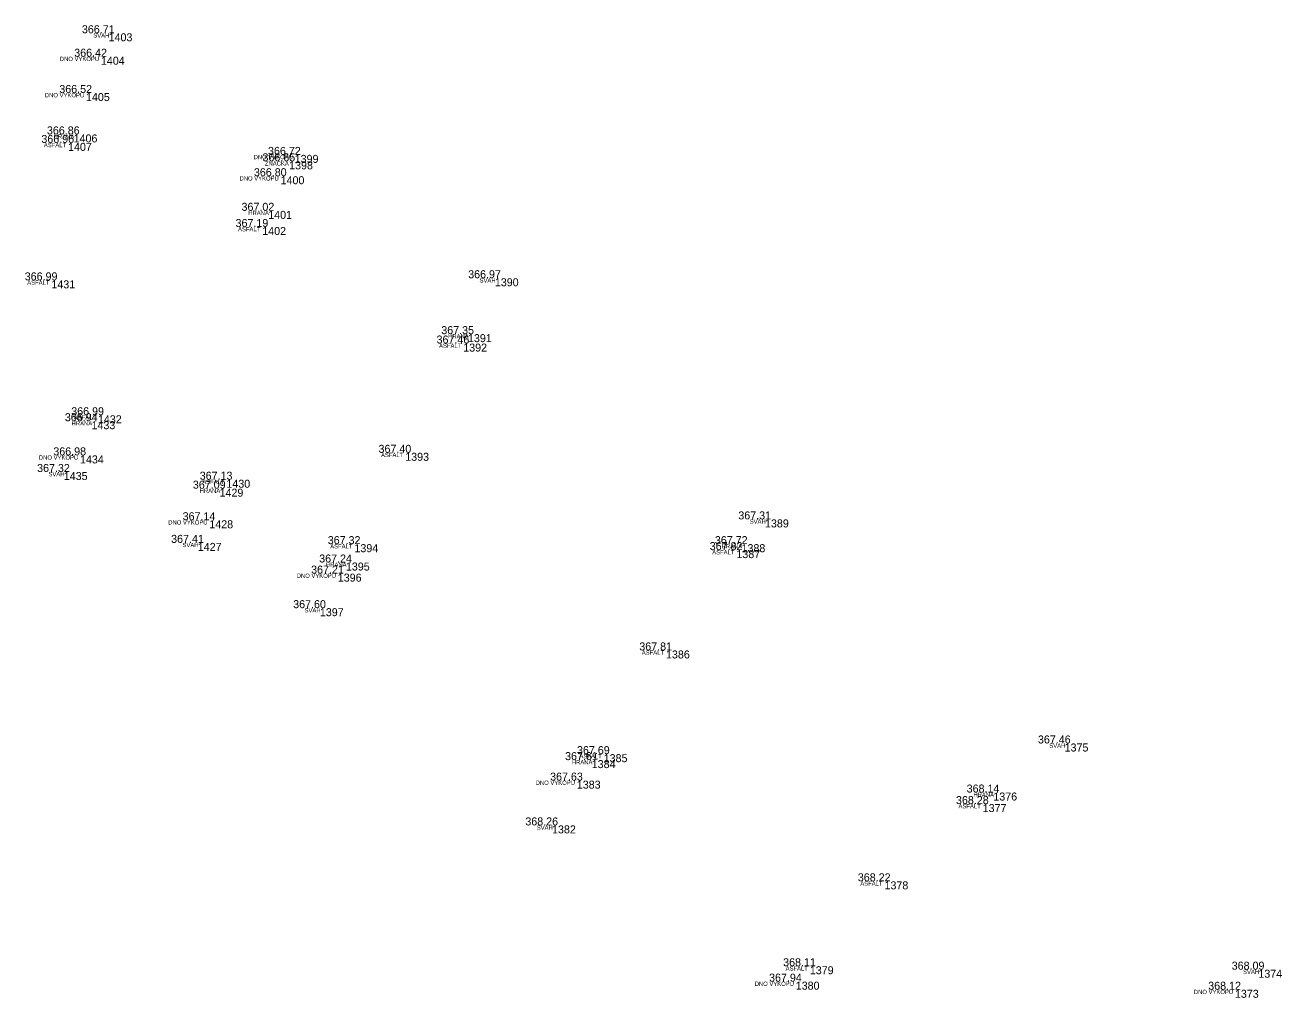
# Model space of a CAD drawing. Extents: x -597865 to -597551, y -1151663 to -1149883.
# Drawn here: x -597649.41 to -597619.96, y -1150439.73 to -1150416.94 of the extents above; entities that cross this region are included whole.
import ezdxf

# ---------------------------------------------------------------- set-up
doc = ezdxf.new("R2010")
doc.units = 0
for name, color, linetype in [('Vrstva 11', 7, 'Continuous'), ('Vrstva 12', 7, 'Continuous'), ('Vrstva 13', 7, 'Continuous'), ('Vrstva 14', 7, 'Continuous')]:
    doc.layers.add(name, color=color, linetype=linetype)

msp = doc.modelspace()

# ---------------------------------------------------------------- linework, layer by layer
at = {"layer": 'Vrstva 11'}
for p, q in [((-597647.45, -1150417.13), (-597647.45, -1150417.13)), ((-597647.63, -1150417.68), (-597647.63, -1150417.68)), ((-597647.98, -1150418.53), (-597647.98, -1150418.53)), ((-597648.4, -1150419.7), (-597648.4, -1150419.7)), ((-597648.27, -1150419.5), (-597648.27, -1150419.5)), ((-597643.09, -1150419.98), (-597643.09, -1150419.98)), ((-597643.22, -1150420.13), (-597643.22, -1150420.13)), ((-597643.42, -1150420.48), (-597643.42, -1150420.48)), ((-597643.71, -1150421.29), (-597643.71, -1150421.29)), ((-597643.85, -1150421.67), (-597643.85, -1150421.67)), ((-597648.79, -1150422.92), (-597648.79, -1150422.92)), ((-597638.4, -1150422.87), (-597638.4, -1150422.87)), ((-597639.14, -1150424.4), (-597639.14, -1150424.4)), ((-597639.03, -1150424.18), (-597639.03, -1150424.18)), ((-597647.85, -1150426.22), (-597647.85, -1150426.22)), ((-597647.7, -1150426.08), (-597647.7, -1150426.08)), ((-597648.12, -1150427.02), (-597648.12, -1150427.02)), ((-597640.5, -1150426.96), (-597640.5, -1150426.96)), ((-597648.5, -1150427.41), (-597648.5, -1150427.41)), ((-597644.69, -1150427.59), (-597644.69, -1150427.59)), ((-597644.85, -1150427.8), (-597644.85, -1150427.8)), ((-597645.09, -1150428.54), (-597645.09, -1150428.54)), ((-597632.07, -1150428.52), (-597632.07, -1150428.52)), ((-597645.36, -1150429.07), (-597645.36, -1150429.07)), ((-597641.69, -1150429.1), (-597641.69, -1150429.1)), ((-597632.62, -1150429.1), (-597632.62, -1150429.1)), ((-597632.74, -1150429.24), (-597632.74, -1150429.24)), ((-597641.89, -1150429.53), (-597641.89, -1150429.53)), ((-597642.08, -1150429.79), (-597642.08, -1150429.79)), ((-597642.5, -1150430.6), (-597642.5, -1150430.6)), ((-597634.39, -1150431.59), (-597634.39, -1150431.59)), ((-597625.05, -1150433.77), (-597625.05, -1150433.77)), ((-597636.13, -1150434.16), (-597636.13, -1150434.16)), ((-597635.85, -1150434.02), (-597635.85, -1150434.02)), ((-597636.48, -1150434.64), (-597636.48, -1150434.64)), ((-597626.72, -1150434.92), (-597626.72, -1150434.92)), ((-597626.97, -1150435.19), (-597626.97, -1150435.19)), ((-597637.06, -1150435.69), (-597637.06, -1150435.69)), ((-597629.27, -1150437), (-597629.27, -1150437)), ((-597631.02, -1150438.99), (-597631.02, -1150438.99)), ((-597620.51, -1150439.07), (-597620.51, -1150439.07)), ((-597631.35, -1150439.35), (-597631.35, -1150439.35)), ((-597621.06, -1150439.54), (-597621.06, -1150439.54))]:
    msp.add_line(p, q, dxfattribs=at)

# ---------------------------------------------------------------- texts
at = {"layer": 'Vrstva 12'}
for s, p in [('366.71 ', (-597648.075, -1150417.13)), ('366.42 ', (-597648.255, -1150417.68)), ('366.52 ', (-597648.605, -1150418.53)), ('366.86 ', (-597648.895, -1150419.5)), ('366.96 ', (-597649.025, -1150419.7)), ('366.65 ', (-597643.845, -1150420.13)), ('366.72 ', (-597643.715, -1150419.98)), ('366.80 ', (-597644.045, -1150420.48)), ('367.02 ', (-597644.335, -1150421.29)), ('367.19 ', (-597644.475, -1150421.67)), ('366.97 ', (-597639.025, -1150422.87)), ('366.99 ', (-597649.415, -1150422.92)), ('367.35 ', (-597639.655, -1150424.18)), ('367.46 ', (-597639.765, -1150424.4)), ('366.99 ', (-597648.325, -1150426.08)), ('366.94 ', (-597648.475, -1150426.22)), ('367.40 ', (-597641.125, -1150426.96)), ('366.98 ', (-597648.745, -1150427.02)), ('367.32 ', (-597649.125, -1150427.41)), ('367.13 ', (-597645.315, -1150427.59)), ('367.09 ', (-597645.475, -1150427.8)), ('367.14 ', (-597645.715, -1150428.54)), ('367.31 ', (-597632.695, -1150428.52)), ('367.41 ', (-597645.985, -1150429.07)), ('367.32 ', (-597642.315, -1150429.1)), ('367.82 ', (-597633.365, -1150429.24)), ('367.72 ', (-597633.245, -1150429.1)), ('367.24 ', (-597642.515, -1150429.53)), ('367.21 ', (-597642.705, -1150429.79)), ('367.60 ', (-597643.125, -1150430.6)), ('367.81 ', (-597635.015, -1150431.59)), ('367.46 ', (-597625.675, -1150433.77)), ('367.69 ', (-597636.475, -1150434.02)), ('367.61 ', (-597636.755, -1150434.16)), ('367.63 ', (-597637.105, -1150434.64)), ('368.14 ', (-597627.345, -1150434.92)), ('368.28 ', (-597627.595, -1150435.19)), ('368.26 ', (-597637.685, -1150435.69)), ('368.22 ', (-597629.895, -1150437)), ('368.11 ', (-597631.645, -1150438.99)), ('368.09 ', (-597621.135, -1150439.07)), ('367.94 ', (-597631.975, -1150439.35)), ('368.12 ', (-597621.685, -1150439.54))]:
    msp.add_text(s, height=0.1875, dxfattribs=at).set_placement(p)
at = {"layer": 'Vrstva 13'}
for s, p in [('1403', (-597647.45, -1150417.318)), ('1404', (-597647.63, -1150417.867)), ('1405', (-597647.98, -1150418.718)), ('1407', (-597648.4, -1150419.887)), ('1406', (-597648.27, -1150419.688)), ('1399', (-597643.09, -1150420.167)), ('1398', (-597643.22, -1150420.318)), ('1400', (-597643.42, -1150420.667)), ('1401', (-597643.71, -1150421.478)), ('1402', (-597643.85, -1150421.857)), ('1431', (-597648.79, -1150423.107)), ('1390', (-597638.4, -1150423.058)), ('1392', (-597639.14, -1150424.588)), ('1391', (-597639.03, -1150424.367)), ('1433', (-597647.85, -1150426.407)), ('1432', (-597647.7, -1150426.268)), ('1434', (-597648.12, -1150427.208)), ('1393', (-597640.5, -1150427.147)), ('1435', (-597648.5, -1150427.597)), ('1430', (-597644.69, -1150427.778)), ('1429', (-597644.85, -1150427.988)), ('1428', (-597645.09, -1150428.728)), ('1389', (-597632.07, -1150428.708)), ('1427', (-597645.36, -1150429.258)), ('1394', (-597641.69, -1150429.288)), ('1388', (-597632.62, -1150429.288)), ('1387', (-597632.74, -1150429.427)), ('1395', (-597641.89, -1150429.718)), ('1396', (-597642.08, -1150429.978)), ('1397', (-597642.5, -1150430.788)), ('1386', (-597634.39, -1150431.778)), ('1375', (-597625.05, -1150433.958)), ('1384', (-597636.13, -1150434.347)), ('1385', (-597635.85, -1150434.208)), ('1383', (-597636.48, -1150434.828)), ('1376', (-597626.72, -1150435.107)), ('1377', (-597626.97, -1150435.377)), ('1382', (-597637.06, -1150435.877)), ('1378', (-597629.27, -1150437.188)), ('1379', (-597631.02, -1150439.177)), ('1374', (-597620.51, -1150439.258)), ('1380', (-597631.35, -1150439.538)), ('1373', (-597621.06, -1150439.728))]:
    msp.add_text(s, height=0.1875, dxfattribs=at).set_placement(p)
at = {"layer": 'Vrstva 14'}
for s, p in [('SVAH', (-597647.808, -1150417.23)), ('DNO VYKOPU', (-597648.593, -1150417.78)), ('DNO VYKOPU', (-597648.943, -1150418.63)), ('ASFALT', (-597648.967, -1150419.8)), ('HRANA', (-597648.737, -1150419.6)), ('DNO VYKOPU', (-597644.052, -1150420.08)), ('ZNACKA', (-597643.787, -1150420.23)), ('DNO VYKOPU', (-597644.383, -1150420.58)), ('HRANA', (-597644.177, -1150421.39)), ('ASFALT', (-597644.417, -1150421.77)), ('ASFALT', (-597649.357, -1150423.02)), ('SVAH', (-597638.758, -1150422.97)), ('ASFALT', (-597639.707, -1150424.5)), ('HRANA', (-597639.497, -1150424.28)), ('HRANA', (-597648.317, -1150426.32)), ('ASFALT', (-597648.267, -1150426.18)), ('DNO VYKOPU', (-597649.083, -1150427.12)), ('ASFALT', (-597641.067, -1150427.06)), ('SVAH', (-597648.858, -1150427.51)), ('ASFALT', (-597645.257, -1150427.69)), ('HRANA', (-597645.317, -1150427.9)), ('DNO VYKOPU', (-597646.052, -1150428.64)), ('SVAH', (-597632.428, -1150428.62)), ('SVAH', (-597645.718, -1150429.17)), ('ASFALT', (-597642.257, -1150429.2)), ('HRANA', (-597633.087, -1150429.2)), ('ASFALT', (-597633.307, -1150429.34)), ('HRANA', (-597642.357, -1150429.63)), ('DNO VYKOPU', (-597643.042, -1150429.89)), ('SVAH', (-597642.858, -1150430.7)), ('ASFALT', (-597634.957, -1150431.69)), ('SVAH', (-597625.408, -1150433.87)), ('HRANA', (-597636.597, -1150434.26)), ('ASFALT', (-597636.417, -1150434.12)), ('DNO VYKOPU', (-597637.443, -1150434.74)), ('HRANA', (-597627.187, -1150435.02)), ('ASFALT', (-597627.537, -1150435.29)), ('SVAH', (-597637.418, -1150435.79)), ('ASFALT', (-597629.837, -1150437.1)), ('ASFALT', (-597631.587, -1150439.09)), ('SVAH', (-597620.868, -1150439.17)), ('DNO VYKOPU', (-597632.312, -1150439.45)), ('DNO VYKOPU', (-597622.022, -1150439.64))]:
    msp.add_text(s, height=0.1, dxfattribs=at).set_placement(p)

doc.saveas('drawing.dxf')
